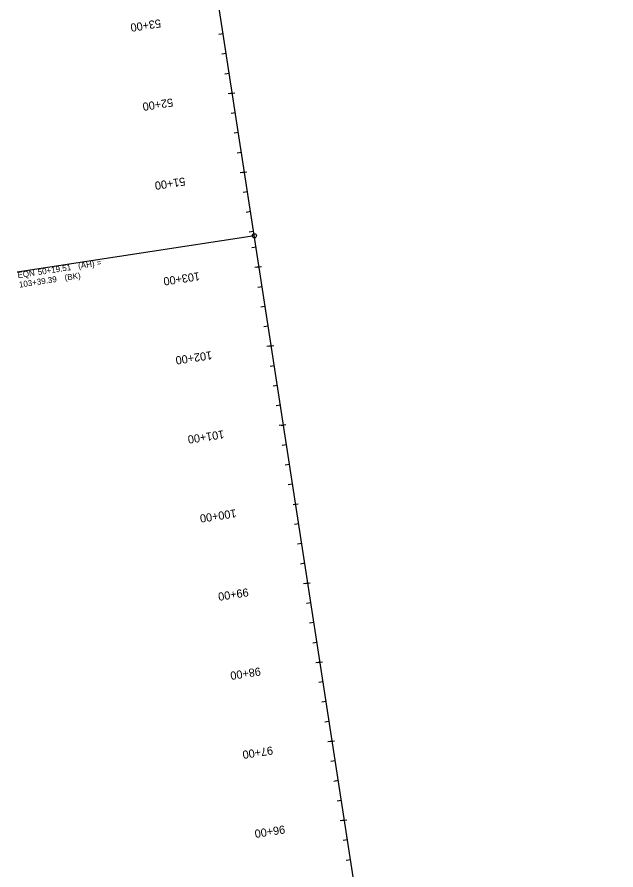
# Model space of a CAD drawing. Extents: x 11526485 to 11527255, y 9590594 to 9599170.
# Drawn here: x 11526504 to 11527252, y 9592749 to 9593816 of the extents above; entities that cross this region are included whole.
import ezdxf

# ---------------------------------------------------------------- set-up
doc = ezdxf.new("R2010")
doc.units = 0
for name, color, linetype in [('Alignment', 7, 'Continuous'), ('Default', 7, 'Continuous'), ('TextAlignment', 7, 'Continuous'), ('TextAlignmentLrg', 7, 'Continuous'), ('TextAlignmentSml', 7, 'Continuous')]:
    doc.layers.add(name, color=color, linetype=linetype)

msp = doc.modelspace()

# ---------------------------------------------------------------- linework, layer by layer
at = {"layer": 'Alignment'}
msp.add_line((11527252.3, 9590607.6), (11526645, 9594551), dxfattribs=at)
at = {"layer": 'Default'}
msp.add_line((11527252.3, 9590607.6), (11526645, 9594551), dxfattribs=at)
at = {"layer": 'TextAlignment'}
msp.add_line((11526800.4, 9593542.4), (11526503.9, 9593496.8), dxfattribs=at)
msp.add_circle((11526800.4, 9593542.4), 2.67, dxfattribs=at)
at = {"layer": 'TextAlignmentLrg'}
for p, q in [((11526772.9, 9593720.8), (11526767.5, 9593720)), ((11526788.1, 9593622), (11526782.7, 9593621.1)), ((11526806.4, 9593503.5), (11526801, 9593502.7)), ((11526821.6, 9593404.7), (11526816.2, 9593403.8)), ((11526836.8, 9593305.8), (11526831.4, 9593305)), ((11526849, 9593206.5), (11526855, 9593207.4)), ((11526867.2, 9593108.1), (11526861.8, 9593107.3)), ((11526882.5, 9593009.3), (11526877.1, 9593008.5)), ((11526897.7, 9592910.5), (11526892.3, 9592909.6)), ((11526912.9, 9592811.6), (11526907.5, 9592810.8))]:
    msp.add_line(p, q, dxfattribs=at)
at = {"layer": 'TextAlignmentSml'}
for p, q in [((11526761.5, 9593794.9), (11526756.1, 9593794.1)), ((11526765.3, 9593770.2), (11526759.9, 9593769.4)), ((11526769.1, 9593745.5), (11526763.7, 9593744.7)), ((11526769.9, 9593720.3), (11526775.9, 9593721.3)), ((11526776.7, 9593696.1), (11526771.3, 9593695.3)), ((11526780.5, 9593671.4), (11526775.1, 9593670.6)), ((11526784.3, 9593646.7), (11526778.9, 9593645.8)), ((11526785.1, 9593621.5), (11526791.1, 9593622.4)), ((11526791.9, 9593597.3), (11526786.5, 9593596.4)), ((11526795.7, 9593572.6), (11526790.3, 9593571.7)), ((11526799.5, 9593547.8), (11526794.1, 9593547)), ((11526802.6, 9593528.2), (11526797.2, 9593527.4)), ((11526803.3, 9593503), (11526809.4, 9593504)), ((11526810.2, 9593478.8), (11526804.8, 9593477.9)), ((11526814, 9593454.1), (11526808.6, 9593453.2)), ((11526817.8, 9593429.4), (11526812.4, 9593428.5)), ((11526818.6, 9593404.2), (11526824.6, 9593405.1)), ((11526825.4, 9593379.9), (11526820, 9593379.1)), ((11526829.2, 9593355.2), (11526823.8, 9593354.4)), ((11526833, 9593330.5), (11526827.6, 9593329.7)), ((11526833.8, 9593305.4), (11526839.8, 9593306.3)), ((11526840.6, 9593281.1), (11526835.2, 9593280.3)), ((11526844.4, 9593256.4), (11526839, 9593255.6)), ((11526848.2, 9593231.7), (11526842.8, 9593230.9)), ((11526849, 9593206.5), (11526855, 9593207.4)), ((11526855.8, 9593182.3), (11526850.4, 9593181.4)), ((11526859.6, 9593157.6), (11526854.2, 9593156.7)), ((11526863.4, 9593132.9), (11526858, 9593132)), ((11526864.2, 9593107.7), (11526870.3, 9593108.6)), ((11526871, 9593083.4), (11526865.6, 9593082.6)), ((11526874.8, 9593058.7), (11526869.5, 9593057.9)), ((11526878.7, 9593034), (11526873.3, 9593033.2)), ((11526879.4, 9593008.8), (11526885.5, 9593009.8)), ((11526886.3, 9592984.6), (11526880.9, 9592983.8)), ((11526890.1, 9592959.9), (11526884.7, 9592959.1)), ((11526893.9, 9592935.2), (11526888.5, 9592934.4)), ((11526894.7, 9592910), (11526900.7, 9592910.9)), ((11526901.5, 9592885.8), (11526896.1, 9592884.9)), ((11526905.3, 9592861.1), (11526899.9, 9592860.2)), ((11526909.1, 9592836.4), (11526903.7, 9592835.5)), ((11526909.9, 9592811.2), (11526915.9, 9592812.1)), ((11526916.7, 9592786.9), (11526911.3, 9592786.1)), ((11526920.5, 9592762.2), (11526915.1, 9592761.4))]:
    msp.add_line(p, q, dxfattribs=at)

# ---------------------------------------------------------------- texts
at = {"layer": 'TextAlignment'}
for s, p in [('50+19.51', (11526530.3, 9593493.2)), ('(AH) = ', (11526580.8, 9593501)), ('EQN ', (11526505, 9593489.3)), ('(BK)', (11526563.9, 9593486.3)), ('103+39.39', (11526506.8, 9593477.5))]:
    msp.add_text(s, height=7.5, rotation=8.7543, dxfattribs=at).set_placement(p)
at = {"layer": 'TextAlignmentLrg'}
msp.add_text('100+00', height=10.2, rotation=188.7543, dxfattribs=at).set_placement((11526777.1, 9593200.6))
at = {"layer": 'TextAlignmentSml'}
for s, p in [('53+00', (11526682.8, 9593813.3)), ('52+00', (11526698, 9593714.4)), ('51+00', (11526713.2, 9593615.6)), ('103+00', (11526731.5, 9593497.1)), ('102+00', (11526746.7, 9593398.3)), ('101+00', (11526761.9, 9593299.4)), ('100+00', (11526777.1, 9593200.6)), ('99+00', (11526792.3, 9593101.8)), ('98+00', (11526807.6, 9593002.9)), ('97+00', (11526822.8, 9592904.1)), ('96+00', (11526838, 9592805.3))]:
    msp.add_text(s, height=10.2, rotation=188.7543, dxfattribs=at).set_placement(p)

doc.saveas('drawing.dxf')
